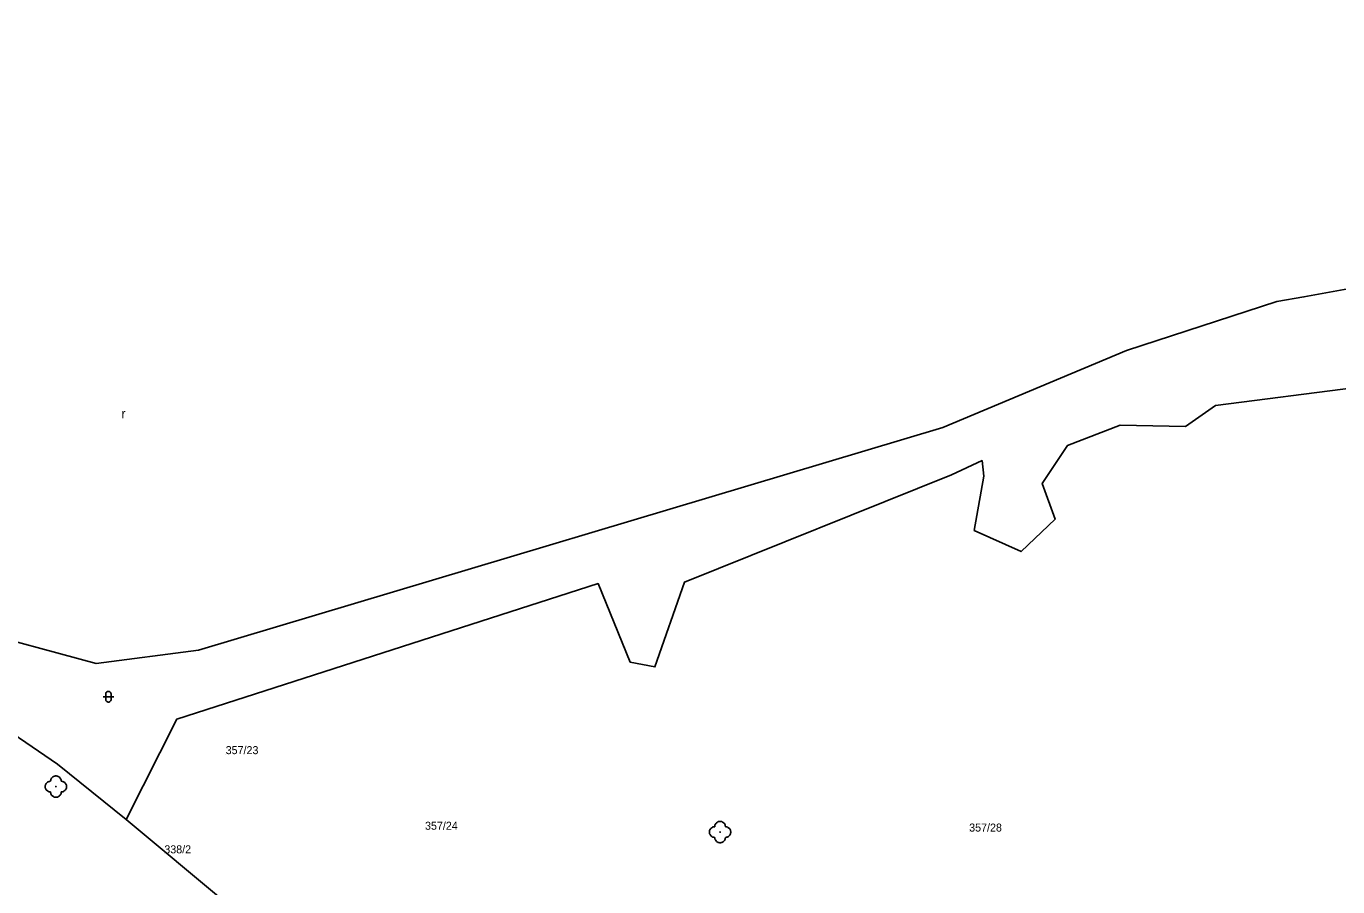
# Model space of a CAD drawing. Extents: x -836739 to -835945, y -1070775 to -1070126.
# Drawn here: x -836580.9 to -836458, y -1070206.4 to -1070125.8 of the extents above; entities that cross this region are included whole.
import ezdxf

# ---------------------------------------------------------------- set-up
doc = ezdxf.new("R2010")
doc.units = 0
for name, color, linetype in [('BodPole_mer', 7, 'Continuous'), ('OstPloch_hranice', 7, 'Continuous'), ('OstPloch_kody', 7, 'Continuous'), ('RuianPar_popis', 7, 'Continuous'), ('Stavby_linie', 7, 'Continuous'), ('Zelen_body', 7, 'Continuous')]:
    doc.layers.add(name, color=color, linetype=linetype)

msp = doc.modelspace()

# ---------------------------------------------------------------- linework, layer by layer
at = {"layer": 'BodPole_mer'}
for p, q in [((-836463.68, -1070151.54), (-836463.68, -1070151.54)), ((-836461.16, -1070151.13), (-836461.16, -1070151.13)), ((-836477.77, -1070156.14), (-836477.77, -1070156.14)), ((-836469.44, -1070161.28), (-836469.44, -1070161.28)), ((-836494.99, -1070163.36), (-836494.99, -1070163.36)), ((-836478.36, -1070163.13), (-836478.36, -1070163.13)), ((-836472.25, -1070163.25), (-836472.25, -1070163.25)), ((-836483.32, -1070165.03), (-836483.32, -1070165.03)), ((-836491.31, -1070166.45), (-836491.31, -1070166.45)), ((-836494.17, -1070167.78), (-836494.17, -1070167.78)), ((-836491.14, -1070167.9), (-836491.14, -1070167.9)), ((-836485.69, -1070168.61), (-836485.69, -1070168.61)), ((-836484.46, -1070171.93), (-836484.46, -1070171.93)), ((-836492.05, -1070172.99), (-836492.05, -1070172.99)), ((-836487.66, -1070174.97), (-836487.66, -1070174.97)), ((-836527.29, -1070177.98), (-836527.29, -1070177.98)), ((-836519.2, -1070177.84), (-836519.2, -1070177.84)), ((-836564.73, -1070184.21), (-836564.73, -1070184.21)), ((-836574.34, -1070185.45), (-836574.34, -1070185.45)), ((-836524.29, -1070185.33), (-836524.29, -1070185.33)), ((-836521.97, -1070185.78), (-836521.97, -1070185.78)), ((-836566.77, -1070190.66), (-836566.77, -1070190.66)), ((-836577.96, -1070194.89), (-836577.96, -1070194.89)), ((-836578.1, -1070196.99), (-836578.1, -1070196.99)), ((-836571.5, -1070200.08), (-836571.5, -1070200.08)), ((-836515.86, -1070201.25), (-836515.86, -1070201.25))]:
    msp.add_line(p, q, dxfattribs=at)
at = {"layer": 'OstPloch_hranice'}
msp.add_line((-836494.99, -1070163.36), (-836564.73, -1070184.21), dxfattribs=at)
for points in [[(-836404.38, -1070205.23), (-836402.5, -1070201.83), (-836397.02, -1070198.53), (-836393.57, -1070195.71), (-836388.95, -1070189.69), (-836384.03, -1070176.12), (-836378.56, -1070158.89), (-836372.13, -1070144.62), (-836365.93, -1070132.95), (-836364.19, -1070126.7), (-836369.77, -1070125.77), (-836373.7, -1070126.07), (-836388.8, -1070131.24), (-836403.54, -1070136.21), (-836415.72, -1070138.17), (-836422.93, -1070140.33), (-836427.24, -1070141.62), (-836436.7, -1070143.96), (-836447.77, -1070148.66), (-836452.9, -1070149.61), (-836461.16, -1070151.13), (-836463.68, -1070151.54), (-836477.77, -1070156.14), (-836494.99, -1070163.36)], [(-836494.17, -1070167.78), (-836491.31, -1070166.45), (-836491.14, -1070167.9), (-836492.05, -1070172.99), (-836487.66, -1070174.97), (-836484.46, -1070171.93), (-836485.69, -1070168.61), (-836483.32, -1070165.03), (-836478.36, -1070163.13), (-836472.25, -1070163.25), (-836469.44, -1070161.28), (-836456.29, -1070159.61), (-836451.7, -1070153.75), (-836452.9, -1070149.61)], [(-836564.73, -1070184.21), (-836574.34, -1070185.45), (-836586.56, -1070182.14), (-836613.97, -1070167.29)], [(-836494.17, -1070167.78), (-836519.2, -1070177.84), (-836521.97, -1070185.78), (-836524.29, -1070185.33), (-836527.29, -1070177.98), (-836566.77, -1070190.66), (-836571.5, -1070200.08)]]:
    msp.add_lwpolyline(points, dxfattribs=at)
at = {"layer": 'OstPloch_kody'}
for p, q in [((-836573.68, -1070188.57), (-836572.68, -1070188.57)), ((-836573.43, -1070188.82), (-836573.43, -1070188.32)), ((-836572.93, -1070188.32), (-836572.93, -1070188.82))]:
    msp.add_line(p, q, dxfattribs=at)
for points in [[(-836573.18, -1070188.07), (-836573.23, -1070188.07), (-836573.27, -1070188.09), (-836573.32, -1070188.11), (-836573.36, -1070188.14), (-836573.39, -1070188.18), (-836573.41, -1070188.23), (-836573.43, -1070188.27), (-836573.43, -1070188.32)], [(-836573.18, -1070188.07), (-836573.13, -1070188.07), (-836573.09, -1070188.09), (-836573.04, -1070188.11), (-836573, -1070188.14), (-836572.97, -1070188.18), (-836572.95, -1070188.23), (-836572.93, -1070188.27), (-836572.93, -1070188.32)], [(-836573.18, -1070189.07), (-836573.23, -1070189.07), (-836573.27, -1070189.05), (-836573.32, -1070189.03), (-836573.36, -1070189), (-836573.39, -1070188.96), (-836573.41, -1070188.91), (-836573.43, -1070188.87), (-836573.43, -1070188.82)], [(-836572.93, -1070188.82), (-836572.93, -1070188.87), (-836572.95, -1070188.91), (-836572.97, -1070188.96), (-836573, -1070189), (-836573.04, -1070189.03), (-836573.09, -1070189.05), (-836573.13, -1070189.07), (-836573.18, -1070189.07)]]:
    msp.add_lwpolyline(points, dxfattribs=at)
at = {"layer": 'RuianPar_popis'}
for p, q in [((-836562.19, -1070193.95), (-836562.19, -1070193.95)), ((-836543.51, -1070201.03), (-836543.51, -1070201.03)), ((-836492.52, -1070201.2), (-836492.52, -1070201.2)), ((-836567.94, -1070203.24), (-836567.94, -1070203.24))]:
    msp.add_line(p, q, dxfattribs=at)
at = {"layer": 'Stavby_linie'}
msp.add_lwpolyline([(-836646.79, -1070164.47), (-836635.17, -1070166.04), (-836623.33, -1070167.88), (-836615.58, -1070169.1), (-836607.83, -1070173.77), (-836593.75, -1070183.78), (-836585.2, -1070189.95), (-836577.96, -1070194.89), (-836571.5, -1070200.08), (-836562.11, -1070207.9), (-836555.43, -1070213.46), (-836552.63, -1070222.02), (-836550.05, -1070228.71)], dxfattribs=at)
at = {"layer": 'Zelen_body'}
for p, q in [((-836578.1, -1070196.99), (-836578.1, -1070196.99)), ((-836515.86, -1070201.25), (-836515.86, -1070201.25))]:
    msp.add_line(p, q, dxfattribs=at)
for points in [[(-836578.6, -1070197.49), (-836578.65, -1070197.49), (-836578.7, -1070197.48), (-836578.75, -1070197.47), (-836578.8, -1070197.45), (-836578.84, -1070197.43), (-836578.89, -1070197.4), (-836578.93, -1070197.36), (-836578.97, -1070197.32), (-836579.01, -1070197.28), (-836579.04, -1070197.23), (-836579.06, -1070197.19), (-836579.08, -1070197.14), (-836579.09, -1070197.09), (-836579.1, -1070197.04), (-836579.1, -1070196.99), (-836579.1, -1070196.94), (-836579.09, -1070196.89), (-836579.08, -1070196.84), (-836579.06, -1070196.79), (-836579.04, -1070196.75), (-836579.01, -1070196.7), (-836578.97, -1070196.66), (-836578.93, -1070196.62), (-836578.89, -1070196.58), (-836578.84, -1070196.55), (-836578.8, -1070196.53), (-836578.75, -1070196.51), (-836578.7, -1070196.5), (-836578.65, -1070196.49), (-836578.6, -1070196.49)], [(-836578.6, -1070196.49), (-836578.6, -1070196.44), (-836578.59, -1070196.39), (-836578.58, -1070196.34), (-836578.56, -1070196.29), (-836578.54, -1070196.25), (-836578.51, -1070196.2), (-836578.47, -1070196.16), (-836578.43, -1070196.12), (-836578.39, -1070196.08), (-836578.34, -1070196.05), (-836578.3, -1070196.03), (-836578.25, -1070196.01), (-836578.2, -1070196), (-836578.15, -1070195.99), (-836578.1, -1070195.99), (-836578.05, -1070195.99), (-836578, -1070196), (-836577.95, -1070196.01), (-836577.9, -1070196.03), (-836577.86, -1070196.05), (-836577.81, -1070196.08), (-836577.77, -1070196.12), (-836577.73, -1070196.16), (-836577.69, -1070196.2), (-836577.66, -1070196.25), (-836577.64, -1070196.29), (-836577.62, -1070196.34), (-836577.61, -1070196.39), (-836577.6, -1070196.44), (-836577.6, -1070196.49)], [(-836577.6, -1070196.49), (-836577.55, -1070196.49), (-836577.5, -1070196.5), (-836577.45, -1070196.51), (-836577.4, -1070196.53), (-836577.36, -1070196.55), (-836577.31, -1070196.58), (-836577.27, -1070196.62), (-836577.23, -1070196.66), (-836577.19, -1070196.7), (-836577.16, -1070196.75), (-836577.14, -1070196.79), (-836577.12, -1070196.84), (-836577.11, -1070196.89), (-836577.1, -1070196.94), (-836577.1, -1070196.99), (-836577.1, -1070197.04), (-836577.11, -1070197.09), (-836577.12, -1070197.14), (-836577.14, -1070197.19), (-836577.16, -1070197.23), (-836577.19, -1070197.28), (-836577.23, -1070197.32), (-836577.27, -1070197.36), (-836577.31, -1070197.4), (-836577.36, -1070197.43), (-836577.4, -1070197.45), (-836577.45, -1070197.47), (-836577.5, -1070197.48), (-836577.55, -1070197.49), (-836577.6, -1070197.49)], [(-836577.6, -1070197.49), (-836577.6, -1070197.54), (-836577.61, -1070197.59), (-836577.62, -1070197.64), (-836577.64, -1070197.69), (-836577.66, -1070197.73), (-836577.69, -1070197.78), (-836577.73, -1070197.82), (-836577.77, -1070197.86), (-836577.81, -1070197.9), (-836577.86, -1070197.93), (-836577.9, -1070197.95), (-836577.95, -1070197.97), (-836578, -1070197.98), (-836578.05, -1070197.99), (-836578.1, -1070197.99), (-836578.15, -1070197.99), (-836578.2, -1070197.98), (-836578.25, -1070197.97), (-836578.3, -1070197.95), (-836578.34, -1070197.93), (-836578.39, -1070197.9), (-836578.43, -1070197.86), (-836578.47, -1070197.82), (-836578.51, -1070197.78), (-836578.54, -1070197.73), (-836578.56, -1070197.69), (-836578.58, -1070197.64), (-836578.59, -1070197.59), (-836578.6, -1070197.54), (-836578.6, -1070197.49)], [(-836516.36, -1070201.75), (-836516.41, -1070201.75), (-836516.46, -1070201.74), (-836516.51, -1070201.73), (-836516.56, -1070201.71), (-836516.6, -1070201.69), (-836516.65, -1070201.66), (-836516.69, -1070201.62), (-836516.73, -1070201.58), (-836516.77, -1070201.54), (-836516.8, -1070201.49), (-836516.82, -1070201.45), (-836516.84, -1070201.4), (-836516.85, -1070201.35), (-836516.86, -1070201.3), (-836516.86, -1070201.25), (-836516.86, -1070201.2), (-836516.85, -1070201.15), (-836516.84, -1070201.1), (-836516.82, -1070201.05), (-836516.8, -1070201.01), (-836516.77, -1070200.96), (-836516.73, -1070200.92), (-836516.69, -1070200.88), (-836516.65, -1070200.84), (-836516.6, -1070200.81), (-836516.56, -1070200.79), (-836516.51, -1070200.77), (-836516.46, -1070200.76), (-836516.41, -1070200.75), (-836516.36, -1070200.75)], [(-836516.36, -1070200.75), (-836516.36, -1070200.7), (-836516.35, -1070200.65), (-836516.34, -1070200.6), (-836516.32, -1070200.55), (-836516.3, -1070200.51), (-836516.27, -1070200.46), (-836516.23, -1070200.42), (-836516.19, -1070200.38), (-836516.15, -1070200.34), (-836516.1, -1070200.31), (-836516.06, -1070200.29), (-836516.01, -1070200.27), (-836515.96, -1070200.26), (-836515.91, -1070200.25), (-836515.86, -1070200.25), (-836515.81, -1070200.25), (-836515.76, -1070200.26), (-836515.71, -1070200.27), (-836515.66, -1070200.29), (-836515.62, -1070200.31), (-836515.57, -1070200.34), (-836515.53, -1070200.38), (-836515.49, -1070200.42), (-836515.45, -1070200.46), (-836515.42, -1070200.51), (-836515.4, -1070200.55), (-836515.38, -1070200.6), (-836515.37, -1070200.65), (-836515.36, -1070200.7), (-836515.36, -1070200.75)], [(-836515.36, -1070200.75), (-836515.31, -1070200.75), (-836515.26, -1070200.76), (-836515.21, -1070200.77), (-836515.16, -1070200.79), (-836515.12, -1070200.81), (-836515.07, -1070200.84), (-836515.03, -1070200.88), (-836514.99, -1070200.92), (-836514.95, -1070200.96), (-836514.92, -1070201.01), (-836514.9, -1070201.05), (-836514.88, -1070201.1), (-836514.87, -1070201.15), (-836514.86, -1070201.2), (-836514.86, -1070201.25), (-836514.86, -1070201.3), (-836514.87, -1070201.35), (-836514.88, -1070201.4), (-836514.9, -1070201.45), (-836514.92, -1070201.49), (-836514.95, -1070201.54), (-836514.99, -1070201.58), (-836515.03, -1070201.62), (-836515.07, -1070201.66), (-836515.12, -1070201.69), (-836515.16, -1070201.71), (-836515.21, -1070201.73), (-836515.26, -1070201.74), (-836515.31, -1070201.75), (-836515.36, -1070201.75)], [(-836515.36, -1070201.75), (-836515.36, -1070201.8), (-836515.37, -1070201.85), (-836515.38, -1070201.9), (-836515.4, -1070201.95), (-836515.42, -1070201.99), (-836515.45, -1070202.04), (-836515.49, -1070202.08), (-836515.53, -1070202.12), (-836515.57, -1070202.16), (-836515.62, -1070202.19), (-836515.66, -1070202.21), (-836515.71, -1070202.23), (-836515.76, -1070202.24), (-836515.81, -1070202.25), (-836515.86, -1070202.25), (-836515.91, -1070202.25), (-836515.96, -1070202.24), (-836516.01, -1070202.23), (-836516.06, -1070202.21), (-836516.1, -1070202.19), (-836516.15, -1070202.16), (-836516.19, -1070202.12), (-836516.23, -1070202.08), (-836516.27, -1070202.04), (-836516.3, -1070201.99), (-836516.32, -1070201.95), (-836516.34, -1070201.9), (-836516.35, -1070201.85), (-836516.36, -1070201.8), (-836516.36, -1070201.75)]]:
    msp.add_lwpolyline(points, dxfattribs=at)
for centre in [(-836578.1, -1070196.99), (-836515.86, -1070201.25)]:
    msp.add_ellipse(centre, major_axis=(0.025, 0), ratio=0.999997, dxfattribs=at)

# ---------------------------------------------------------------- texts
at = {"layer": 'OstPloch_kody'}
msp.add_text('r', height=0.9, dxfattribs=at).set_placement((-836571.96, -1070162.5))
at = {"layer": 'RuianPar_popis'}
for s, p in [('357/23', (-836562.19, -1070193.95)), ('357/24', (-836543.51, -1070201.03)), ('357/28', (-836492.52, -1070201.2)), ('338/2', (-836567.94, -1070203.24))]:
    msp.add_text(s, height=0.75, dxfattribs=at).set_placement(p)

doc.saveas('drawing.dxf')
